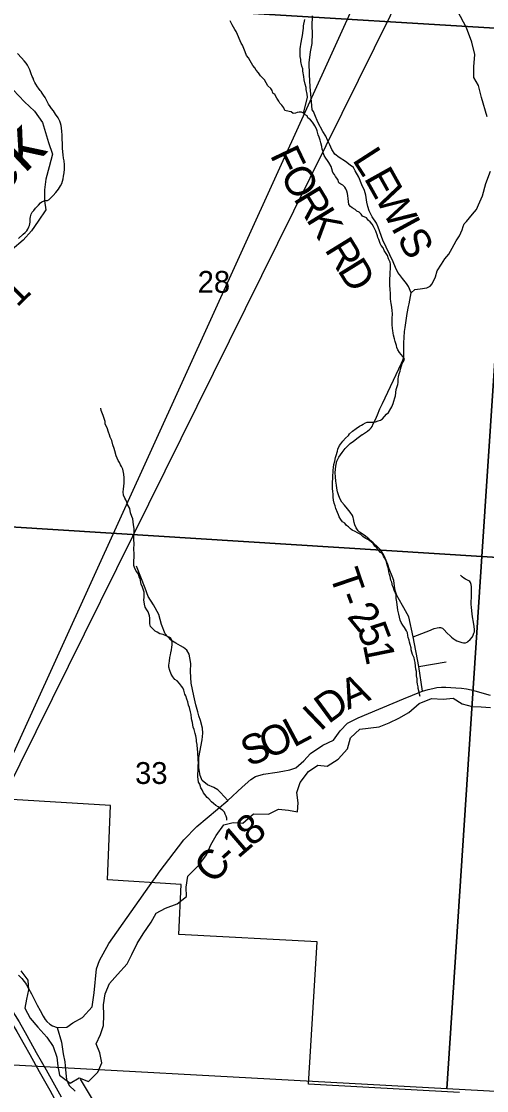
# Model space of a CAD drawing. Extents: x 0 to 45.4, y -2.2 to 22.
# Drawn here: x 5.099 to 5.991, y 15.133 to 17.183 of the extents above; entities that cross this region are included whole.
import ezdxf

# ---------------------------------------------------------------- set-up
doc = ezdxf.new("R2010")
doc.units = 0
for name, color, linetype in [('GM_X_Corporation', 7, 'Continuous'), ('GM_X_County_Road', 7, 'Continuous'), ('GM_X_County_Road_Text', 7, 'Continuous'), ('GM_X_Minor_River', 7, 'Continuous'), ('GM_X_Minor_River_Text', 7, 'Continuous'), ('GM_X_Section_Text', 7, 'Continuous'), ('GM_X_Township_Road', 7, 'Continuous'), ('GM_X_Township_Road_Text', 7, 'Continuous'), ('GM_X_US_Route', 7, 'Continuous'), ('SH_Text', 7, 'Continuous')]:
    doc.layers.add(name, color=color, linetype=linetype)

msp = doc.modelspace()

# ---------------------------------------------------------------- linework, layer by layer
at = {"layer": 'GM_X_Corporation'}
for points in [[(5.0121, 18.2353), (6.1142, 18.166), (6.0488, 17.1677), (4.9524, 17.2347)], [(6.0488, 17.1677), (5.9818, 16.1569), (4.8941, 16.2254), (4.9524, 17.2347)], [(7.1661, 17.098), (7.1036, 16.0876), (5.9818, 16.1569), (6.0488, 17.1677)], [(4.8941, 16.2254), (5.9818, 16.1569), (5.9148, 15.1362), (4.837, 15.1953)], [(5.9818, 16.1569), (7.1036, 16.0876), (7.0412, 15.0748), (5.9148, 15.1362)]]:
    msp.add_lwpolyline(points, close=True, dxfattribs=at)
msp.add_lwpolyline([(5.9392, 15.1293), (5.6491, 15.1452), (5.6657, 15.4185), (5.4004, 15.4324), (5.405, 15.5281), (5.2641, 15.5371), (5.2696, 15.6795), (4.8585, 15.7047)], dxfattribs=at)
at = {"layer": 'GM_X_County_Road'}
for points in [[(5.3539, 15.539), (5.3545, 15.5398), (5.3632, 15.5521), (5.4101, 15.6136), (5.4351, 15.6392), (5.4944, 15.6895), (5.5223, 15.7146), (5.5385, 15.7293), (5.5477, 15.7352), (5.5629, 15.74), (5.5893, 15.7436), (5.6001, 15.7452), (5.6134, 15.748), (5.6248, 15.7521), (5.6405, 15.7656), (5.6534, 15.7793), (5.6765, 15.7952), (5.6973, 15.8047), (5.7098, 15.8226), (5.7242, 15.8374), (5.7446, 15.848), (5.8316, 15.8843), (5.8661, 15.8983), (5.868, 15.899)], [(5.868, 15.899), (5.8786, 15.9021), (5.8876, 15.9042), (5.8956, 15.9058), (5.9043, 15.9064), (5.9125, 15.9064), (5.9223, 15.9061), (5.9317, 15.9055), (5.9427, 15.9047), (5.9521, 15.9034), (5.9612, 15.9016), (5.9709, 15.8991), (5.9819, 15.8958), (5.9976, 15.8914)], [(5.0933, 15.3545), (5.0995, 15.3477), (5.104, 15.3422), (5.1062, 15.3389), (5.1083, 15.3356), (5.1123, 15.3287), (5.1181, 15.3185), (5.1234, 15.3082), (5.1289, 15.2967), (5.1344, 15.2866), (5.1405, 15.2757), (5.144, 15.2696), (5.1474, 15.2658), (5.1531, 15.2605), (5.1581, 15.2572), (5.1671, 15.2539), (5.186, 15.2549), (5.1976, 15.2631), (5.2161, 15.2729), (5.2343, 15.2938), (5.2385, 15.3204), (5.243, 15.3664), (5.2487, 15.3827), (5.2665, 15.4154), (5.3522, 15.5366), (5.3539, 15.539)]]:
    msp.add_lwpolyline(points, dxfattribs=at)
at = {"layer": 'GM_X_Minor_River'}
for points in [[(5.7009, 16.8855), (5.6994, 16.8894), (5.6961, 16.8932), (5.6943, 16.9005), (5.6925, 16.9051), (5.6881, 16.9128), (5.6855, 16.9166), (5.6825, 16.9205), (5.6796, 16.9258), (5.6782, 16.93), (5.6767, 16.9346), (5.6753, 16.9381), (5.675, 16.9434), (5.6728, 16.9503), (5.6714, 16.9552), (5.6696, 16.9614), (5.6678, 16.9656), (5.666, 16.9732), (5.6646, 16.977), (5.6613, 16.9828), (5.6594, 16.9862), (5.6572, 16.9901), (5.6531, 16.9943), (5.6483, 16.9982), (5.6468, 17.002), (5.6431, 17.0036), (5.6397, 17.0071), (5.6356, 17.0087), (5.6314, 17.0088), (5.6276, 17.0081), (5.6242, 17.0074), (5.62, 17.0067), (5.6159, 17.0094), (5.6121, 17.0106), (5.6042, 17.0123), (5.6017, 17.0176), (5.5979, 17.0223), (5.5946, 17.0261), (5.5924, 17.0303), (5.5883, 17.0361), (5.5847, 17.0426), (5.5809, 17.0457), (5.5795, 17.0503), (5.5773, 17.0542), (5.5713, 17.0592), (5.5647, 17.0707), (5.5573, 17.0784), (5.5536, 17.0846), (5.5491, 17.0896), (5.5466, 17.0942), (5.5428, 17.0985), (5.5377, 17.1077), (5.534, 17.1134), (5.5307, 17.1177), (5.5281, 17.1246), (5.5227, 17.1372), (5.5201, 17.1414), (5.5183, 17.1456), (5.5132, 17.1579), (5.5103, 17.1636), (5.5077, 17.1675), (5.5029, 17.1767), (5.4989, 17.184)], [(5.6397, 17.0071), (5.647, 17.0344), (5.6471, 17.0378), (5.6468, 17.0435), (5.6451, 17.0526), (5.6451, 17.0564), (5.643, 17.0629), (5.6412, 17.0709), (5.6402, 17.0774), (5.6385, 17.0877), (5.6382, 17.0919), (5.6368, 17.0969), (5.6346, 17.1064), (5.6347, 17.1102), (5.6333, 17.1156), (5.633, 17.119), (5.6335, 17.1262), (5.6336, 17.1308), (5.634, 17.1346), (5.6348, 17.1395), (5.637, 17.1527), (5.6378, 17.1562), (5.6391, 17.1653), (5.6395, 17.1702), (5.64, 17.1744), (5.6425, 17.1865)], [(5.0831, 17.0516), (5.1049, 17.0287), (5.1238, 17.0112), (5.1389, 16.9891), (5.1448, 16.9701), (5.1508, 16.951), (5.1583, 16.9282), (5.1521, 16.9039), (5.1452, 16.8804), (5.1429, 16.8599), (5.1428, 16.8393), (5.1457, 16.8218), (5.1305, 16.7998), (5.1183, 16.7816), (5.1023, 16.7635), (5.0811, 16.746)], [(5.7282, 16.3923), (5.734, 16.3971), (5.7409, 16.4023), (5.7474, 16.4071), (5.7509, 16.4086), (5.7543, 16.4108), (5.7585, 16.4134), (5.762, 16.4145), (5.7661, 16.4148), (5.7737, 16.4147), (5.7775, 16.415), (5.7832, 16.4172), (5.7874, 16.4186), (5.7912, 16.4212), (5.799, 16.4299), (5.8028, 16.4332), (5.8071, 16.4407), (5.8091, 16.4441), (5.8114, 16.4506), (5.813, 16.4551), (5.815, 16.4615), (5.8159, 16.4653), (5.8176, 16.4775), (5.8204, 16.4869), (5.8212, 16.4907), (5.8214, 16.4979), (5.8222, 16.5013), (5.8234, 16.5074), (5.8254, 16.5123), (5.8258, 16.5161), (5.8291, 16.5271), (5.8322, 16.5324), (5.8334, 16.5365), (5.8304, 16.5404), (5.8271, 16.5446), (5.8241, 16.5481), (5.8204, 16.5531), (5.819, 16.5577), (5.8179, 16.5619), (5.8154, 16.5695), (5.8144, 16.5745), (5.8126, 16.5817), (5.8119, 16.5852), (5.8108, 16.5901), (5.8102, 16.5943), (5.8095, 16.602), (5.8097, 16.613), (5.8103, 16.6232), (5.81, 16.6278), (5.809, 16.6354), (5.8076, 16.6423), (5.8073, 16.6457), (5.8066, 16.6511), (5.8067, 16.656), (5.8064, 16.6594), (5.8058, 16.6708), (5.8055, 16.6754), (5.8053, 16.6845), (5.8054, 16.6883), (5.8059, 16.6978), (5.806, 16.7013), (5.8065, 16.7092), (5.8066, 16.7176), (5.8059, 16.7214), (5.803, 16.7275), (5.8005, 16.7344), (5.7968, 16.7402), (5.7942, 16.744), (5.7924, 16.749), (5.7887, 16.7533), (5.7865, 16.7571), (5.7844, 16.7647), (5.7821, 16.7686), (5.7814, 16.772), (5.7786, 16.7808), (5.7764, 16.7847), (5.7742, 16.79), (5.7716, 16.7942), (5.7675, 16.7989), (5.7642, 16.8016), (5.7605, 16.8062), (5.7529, 16.8094), (5.75, 16.8136), (5.7463, 16.8171), (5.7421, 16.8195), (5.7388, 16.8222), (5.7331, 16.8257), (5.7298, 16.828), (5.7268, 16.8323), (5.7258, 16.8376), (5.7251, 16.8433), (5.7245, 16.8486), (5.7238, 16.8528), (5.7227, 16.8578), (5.7209, 16.862), (5.7187, 16.8655), (5.715, 16.869), (5.7112, 16.8709), (5.7075, 16.8733), (5.7057, 16.8798), (5.7009, 16.8855)], [(5.3142, 16.1962), (5.3151, 16.2064), (5.3152, 16.211), (5.3138, 16.2179), (5.3121, 16.2293), (5.3107, 16.2335), (5.3082, 16.2408), (5.3064, 16.2492), (5.3024, 16.2568), (5.3009, 16.2614), (5.2991, 16.2656), (5.2969, 16.2691), (5.2947, 16.2748), (5.2941, 16.2813), (5.2942, 16.2859), (5.2955, 16.298), (5.2956, 16.3045), (5.2957, 16.3079), (5.2954, 16.3148), (5.2944, 16.3182), (5.293, 16.3243), (5.2904, 16.3297), (5.2886, 16.3331), (5.2867, 16.337), (5.2845, 16.3412), (5.2802, 16.3504), (5.278, 16.3599), (5.2766, 16.3641), (5.2741, 16.371), (5.2723, 16.3798), (5.269, 16.3856), (5.2676, 16.3901), (5.2654, 16.3955), (5.2629, 16.4039), (5.2596, 16.4108), (5.259, 16.4161), (5.2557, 16.4272), (5.2514, 16.4372), (5.2507, 16.4418)], [(5.8634, 15.8888), (5.862, 15.8934), (5.8613, 15.8972), (5.8599, 15.9037), (5.8595, 15.9075), (5.8585, 15.9124), (5.8578, 15.9166), (5.8575, 15.9223), (5.8565, 15.9284), (5.8563, 15.9364), (5.8552, 15.941), (5.8546, 15.9471), (5.8539, 15.9536), (5.8529, 15.9589), (5.8518, 15.9631), (5.8489, 15.9693), (5.8474, 15.9738), (5.8464, 15.9784), (5.8461, 15.9822), (5.8443, 15.9883), (5.8432, 15.9929), (5.8422, 15.9964), (5.8407, 16.0021), (5.8397, 16.0059), (5.839, 16.0105), (5.8375, 16.0143), (5.8353, 16.0178), (5.8335, 16.0212), (5.8302, 16.0255), (5.8272, 16.0305), (5.8254, 16.0351), (5.8226, 16.0465), (5.8208, 16.0541), (5.8198, 16.0599), (5.8191, 16.0644), (5.8188, 16.0702), (5.8174, 16.0763), (5.8172, 16.0835), (5.8161, 16.0869), (5.8139, 16.0927), (5.8121, 16.0973), (5.8107, 16.1011), (5.8089, 16.108), (5.8071, 16.1118), (5.8057, 16.1187), (5.8046, 16.1225), (5.8032, 16.1278), (5.8025, 16.1332), (5.8004, 16.1412), (5.7982, 16.1485), (5.7949, 16.1546), (5.7931, 16.158), (5.7909, 16.1619), (5.7871, 16.1646), (5.7827, 16.1696), (5.7801, 16.1735), (5.7764, 16.177), (5.773, 16.182), (5.7667, 16.1874), (5.7633, 16.1897), (5.7581, 16.1921), (5.7536, 16.1952), (5.7499, 16.1991), (5.7431, 16.2022), (5.739, 16.205), (5.7333, 16.2074), (5.73, 16.2101), (5.7263, 16.2139), (5.7221, 16.2167), (5.7188, 16.2209), (5.7147, 16.2236), (5.711, 16.2283), (5.7084, 16.2333), (5.707, 16.2367), (5.7051, 16.2417), (5.7019, 16.249), (5.7004, 16.2543), (5.6986, 16.2593), (5.6972, 16.265), (5.6966, 16.2711), (5.6963, 16.2772), (5.696, 16.281), (5.6954, 16.2879), (5.6956, 16.3004), (5.696, 16.3061), (5.6958, 16.3129), (5.6963, 16.3179), (5.6963, 16.3224), (5.6972, 16.3278), (5.698, 16.3334), (5.6997, 16.3399), (5.7009, 16.3467), (5.7021, 16.3509), (5.7049, 16.3592), (5.7057, 16.3626), (5.7085, 16.3698), (5.7112, 16.3732), (5.7151, 16.3784), (5.7201, 16.384), (5.7263, 16.3889), (5.7282, 16.3923)], [(5.4926, 15.6513), (5.4926, 15.6551), (5.4916, 15.6593), (5.4897, 15.6628), (5.4879, 15.6666), (5.4849, 15.6701), (5.4808, 15.6732), (5.476, 15.6771), (5.4715, 15.6795), (5.467, 15.6837), (5.4633, 15.6864), (5.4584, 15.6926), (5.4547, 15.6953), (5.4506, 15.7007), (5.4477, 15.7042), (5.4455, 15.7095), (5.4429, 15.7134), (5.4407, 15.7203), (5.4385, 15.7241), (5.4372, 15.7352), (5.4375, 15.7519), (5.4379, 15.7557), (5.4381, 15.7621), (5.4377, 15.7659), (5.4375, 15.7732), (5.4372, 15.7774), (5.4373, 15.7827), (5.4366, 15.7872), (5.436, 15.7968), (5.4346, 15.8025), (5.4347, 15.8059), (5.4329, 15.8135), (5.4318, 15.8177), (5.4301, 15.8254), (5.4279, 15.8296), (5.4265, 15.8391), (5.4255, 15.8433), (5.4251, 15.8468), (5.4241, 15.854), (5.4231, 15.859), (5.4213, 15.8673), (5.4191, 15.8719), (5.4181, 15.8784), (5.4159, 15.8838), (5.4142, 15.8899), (5.4123, 15.8934), (5.4102, 15.901), (5.408, 15.9052), (5.4058, 15.9087), (5.4021, 15.9133), (5.3972, 15.9187), (5.3931, 15.9211), (5.389, 15.9261), (5.3857, 15.9318), (5.3832, 15.9387), (5.3814, 15.9452), (5.3815, 15.949), (5.3824, 15.9562), (5.3836, 15.9634), (5.3848, 15.9683), (5.3853, 15.9721), (5.3865, 15.9782), (5.387, 15.9831), (5.3875, 15.9877), (5.3875, 15.9923), (5.3869, 15.9968), (5.3847, 16.001), (5.3775, 16.0046), (5.3704, 16.0074), (5.364, 16.009), (5.3591, 16.0121), (5.355, 16.0141), (5.3494, 16.0199), (5.346, 16.023), (5.345, 16.0283), (5.3452, 16.039), (5.3445, 16.0432), (5.342, 16.0512), (5.3394, 16.055), (5.3361, 16.06), (5.3346, 16.0654), (5.3337, 16.0738), (5.3341, 16.0783), (5.3339, 16.0886), (5.3329, 16.0928), (5.3311, 16.0982), (5.3281, 16.1039), (5.3278, 16.1073), (5.3264, 16.115), (5.3246, 16.1184), (5.3224, 16.1245), (5.3187, 16.1292), (5.3158, 16.1357), (5.3144, 16.1399), (5.3145, 16.1498), (5.315, 16.1543), (5.3152, 16.1638), (5.3145, 16.1695), (5.3147, 16.1832), (5.3144, 16.1878), (5.3142, 16.1962)], [(5.2568, 15.2776), (5.2562, 15.2974), (5.2593, 15.3186), (5.2677, 15.3384), (5.2829, 15.3558), (5.3012, 15.3762), (5.3103, 15.3937), (5.321, 15.4149), (5.3325, 15.4339), (5.3477, 15.4559), (5.3569, 15.4733), (5.3751, 15.4831), (5.3971, 15.4914), (5.4153, 15.505), (5.4146, 15.5233), (5.4178, 15.5445), (5.4391, 15.565), (5.4535, 15.5854), (5.4619, 15.6044), (5.4719, 15.6219), (5.4871, 15.6423), (5.5045, 15.6468), (5.5235, 15.646), (5.544, 15.6634), (5.5728, 15.6633), (5.5917, 15.6724), (5.6107, 15.6708), (5.6281, 15.6677), (5.6297, 15.6851), (5.6267, 15.7049), (5.6336, 15.7239), (5.6496, 15.7451), (5.6671, 15.7572), (5.6852, 15.7549), (5.7065, 15.7685), (5.724, 15.7882), (5.7301, 15.8094), (5.7476, 15.8261), (5.7848, 15.8305), (5.8037, 15.8381), (5.8227, 15.8471), (5.8417, 15.8577), (5.8614, 15.8751), (5.885, 15.8849), (5.9077, 15.8833), (5.9266, 15.8855), (5.944, 15.8748), (5.9629, 15.8694), (5.9803, 15.8686), (5.9985, 15.8678)], [(5.0974, 15.3625), (5.1109, 15.345), (5.1124, 15.326), (5.1085, 15.3085), (5.1054, 15.291), (5.1152, 15.272), (5.1303, 15.2545), (5.1476, 15.2354), (5.1596, 15.2179), (5.1664, 15.1974), (5.1686, 15.1799), (5.1715, 15.1624), (5.1919, 15.1472), (5.2094, 15.1577), (5.2275, 15.1508), (5.245, 15.1683), (5.2527, 15.1865), (5.249, 15.2055), (5.2422, 15.223), (5.2506, 15.2404), (5.256, 15.2579), (5.2568, 15.2776)], [(5.2111, 15.155), (5.2612, 15.0722), (5.2676, 15.0698), (5.2717, 15.0656), (5.2773, 15.0617), (5.2806, 15.059), (5.2844, 15.0574), (5.2889, 15.0566), (5.2939, 15.0572), (5.2977, 15.0583), (5.3045, 15.0586), (5.309, 15.0574)]]:
    msp.add_lwpolyline(points, dxfattribs=at)
at = {"layer": 'GM_X_Township_Road'}
for p, q in [((5.8502, 16.0033), (5.8835, 16.016)), ((5.8611, 15.9463), (5.9131, 15.9551))]:
    msp.add_line(p, q, dxfattribs=at)
for points in [[(5.9918, 16.9998), (5.9809, 17.0373), (5.9754, 17.0602), (5.9662, 17.0757), (5.9662, 17.084), (5.9662, 17.0958), (5.9681, 17.1196), (5.9626, 17.1434), (5.9525, 17.1708), (5.9292, 17.214)], [(5.8412, 16.6362), (5.8423, 16.6418), (5.846, 16.6624), (5.841, 16.6748), (5.837, 16.6807), (5.8296, 16.6899), (5.8236, 16.6975), (5.8208, 16.7015), (5.8159, 16.711), (5.8117, 16.7223), (5.7916, 16.7639), (5.7829, 16.7886), (5.7795, 16.7964), (5.7717, 16.8083), (5.7688, 16.8133), (5.7659, 16.8197), (5.7633, 16.8279), (5.7612, 16.8364), (5.7591, 16.8496), (5.7569, 16.8587), (5.7514, 16.8695), (5.7458, 16.8846), (5.739, 16.8964), (5.7353, 16.903), (5.7295, 16.9073), (5.7203, 16.9142), (5.7082, 16.9218), (5.7001, 16.9284), (5.694, 16.9377), (5.6901, 16.9461), (5.686, 16.9553), (5.6824, 16.9632), (5.6769, 16.9719), (5.6672, 16.9898), (5.6613, 17.004), (5.6588, 17.0101), (5.6565, 17.0133), (5.6555, 17.0219), (5.6523, 17.0577), (5.6513, 17.0811), (5.6506, 17.1038), (5.6534, 17.1247), (5.6561, 17.1405), (5.6568, 17.1606), (5.6565, 17.1741), (5.6568, 17.1939)], [(5.0929, 16.7668), (5.102, 16.7752), (5.1059, 16.7783), (5.1088, 16.7814), (5.1111, 16.7844), (5.1132, 16.789), (5.1142, 16.7919), (5.1148, 16.795), (5.1153, 16.7983), (5.1155, 16.8016), (5.1155, 16.805), (5.1158, 16.8086), (5.1171, 16.8137), (5.1193, 16.8172), (5.1222, 16.8207), (5.1256, 16.8247), (5.1283, 16.8274), (5.1316, 16.831), (5.1353, 16.835), (5.1379, 16.837), (5.1422, 16.8393), (5.1444, 16.8399), (5.1474, 16.8399), (5.1487, 16.8399), (5.1499, 16.8402), (5.1508, 16.8408), (5.1521, 16.8418), (5.1546, 16.8444), (5.1593, 16.8495), (5.1647, 16.8551), (5.1698, 16.8613), (5.1737, 16.8675), (5.176, 16.8721), (5.1774, 16.8766), (5.1786, 16.881), (5.1797, 16.8864), (5.1806, 16.893), (5.181, 16.8998), (5.1811, 16.9035), (5.181, 16.908), (5.1804, 16.916), (5.1794, 16.9211), (5.1785, 16.9274), (5.1779, 16.9328), (5.1776, 16.9402), (5.1773, 16.9494), (5.1769, 16.9568), (5.1768, 16.9657), (5.1764, 16.972), (5.1757, 16.9788), (5.175, 16.9832), (5.1738, 16.9882), (5.1726, 16.9917), (5.1704, 16.9958), (5.1689, 16.9984), (5.1641, 17.0054), (5.1601, 17.0113), (5.1566, 17.0161), (5.1541, 17.0196), (5.1509, 17.0246), (5.144, 17.037), (5.1412, 17.0417), (5.1387, 17.0456), (5.1368, 17.0485), (5.1349, 17.0505), (5.1316, 17.055), (5.1296, 17.0576), (5.1262, 17.0625), (5.1243, 17.0658), (5.1227, 17.0696), (5.121, 17.074), (5.1194, 17.0775), (5.1176, 17.0827), (5.1146, 17.0902), (5.1104, 17.099), (5.1076, 17.1032), (5.104, 17.1073), (5.0989, 17.1131), (5.0914, 17.1218)], [(5.846, 16.6624), (5.8533, 16.6688), (5.8634, 16.6706), (5.8762, 16.6725), (5.8826, 16.6757), (5.8862, 16.6798), (5.8926, 16.6935), (5.8963, 16.7045), (5.9045, 16.7177), (5.9105, 16.7278), (5.9182, 16.7369), (5.9246, 16.7484), (5.9324, 16.7621), (5.9388, 16.7721), (5.9443, 16.7831), (5.9461, 16.79), (5.9479, 16.795), (5.9525, 16.7996), (5.964, 16.8133), (5.9713, 16.8224), (5.9754, 16.8316), (5.9827, 16.8489), (5.9896, 16.8723), (5.9982, 16.896)], [(5.7686, 16.1874), (5.7647, 16.1907), (5.7562, 16.1977), (5.7472, 16.204), (5.7443, 16.2066), (5.7408, 16.2123), (5.7382, 16.2177), (5.7369, 16.2224), (5.7355, 16.2291), (5.7352, 16.2316), (5.7335, 16.2357), (5.7295, 16.2424), (5.7244, 16.2483), (5.7181, 16.2553), (5.713, 16.2615), (5.7093, 16.2684), (5.7069, 16.2755), (5.7052, 16.2812), (5.7038, 16.2883), (5.703, 16.2941), (5.702, 16.3013), (5.7009, 16.31), (5.7005, 16.3174), (5.7013, 16.3243), (5.7017, 16.33), (5.7037, 16.34), (5.7074, 16.3476), (5.7136, 16.3564), (5.7198, 16.3644), (5.729, 16.3735), (5.7353, 16.3781), (5.7443, 16.3851), (5.7525, 16.3909), (5.7528, 16.3912), (5.7549, 16.3925), (5.7625, 16.3977), (5.7667, 16.401), (5.7694, 16.4037), (5.7715, 16.4066), (5.7736, 16.4112), (5.7778, 16.4199), (5.7816, 16.4288), (5.7863, 16.4399), (5.7909, 16.4505), (5.8276, 16.5279), (5.8301, 16.5338), (5.8313, 16.5373), (5.832, 16.5414), (5.8322, 16.5483), (5.8322, 16.5573), (5.8322, 16.5665), (5.8329, 16.5767), (5.8336, 16.5885), (5.8345, 16.5959), (5.8384, 16.6229), (5.8412, 16.6362)], [(5.8013, 16.142), (5.7963, 16.1539), (5.794, 16.1594), (5.79, 16.1661), (5.7869, 16.1704), (5.7819, 16.1757), (5.7733, 16.1835), (5.7686, 16.1874)], [(5.433, 15.8726), (5.4293, 15.8899), (5.4241, 15.9142), (5.423, 15.9367), (5.4235, 15.9519), (5.422, 15.9625), (5.4204, 15.9701), (5.4159, 15.9777), (5.4098, 15.9826), (5.4037, 15.9857), (5.395, 15.9906), (5.3855, 15.9967), (5.3741, 16.0089), (5.3673, 16.0267), (5.3624, 16.0458), (5.3517, 16.0644), (5.3421, 16.0801), (5.3363, 16.0962), (5.3195, 16.1384)], [(5.8352, 16.0532), (5.8324, 16.0584), (5.821, 16.0781), (5.8179, 16.084), (5.8163, 16.0898), (5.8149, 16.096), (5.8138, 16.1056), (5.8127, 16.1111), (5.8098, 16.1192), (5.8041, 16.1336), (5.8013, 16.142)], [(5.8835, 16.016), (5.886, 16.017), (5.8905, 16.0189), (5.8958, 16.0204), (5.9001, 16.0212), (5.9024, 16.0208), (5.9062, 16.0194), (5.9091, 16.017), (5.9155, 16.0104), (5.9208, 16.0052), (5.9238, 16.0025), (5.9269, 15.9997), (5.9307, 15.9972), (5.9341, 15.9957), (5.9379, 15.9942), (5.9432, 15.9924), (5.9466, 15.9914), (5.9485, 15.9914), (5.9505, 15.9913), (5.9536, 15.993), (5.9551, 15.9942), (5.9593, 15.9982), (5.9638, 16.0028), (5.9653, 16.006), (5.9667, 16.0101), (5.9674, 16.0129), (5.9675, 16.0172), (5.9671, 16.0231), (5.9658, 16.0314), (5.9641, 16.0416), (5.9627, 16.0527), (5.9619, 16.06), (5.9615, 16.0652), (5.9615, 16.0717), (5.9616, 16.0781), (5.9617, 16.0845), (5.9618, 16.0991), (5.9615, 16.1036), (5.9602, 16.1073), (5.9587, 16.109), (5.9568, 16.1105), (5.954, 16.1119), (5.9502, 16.1138), (5.9472, 16.1154), (5.9439, 16.1178), (5.9411, 16.1213)], [(5.868, 15.899), (5.8611, 15.9463), (5.8502, 16.0033), (5.8416, 16.0413), (5.8352, 16.0532)], [(5.4944, 15.6895), (5.4808, 15.7049), (5.4754, 15.71), (5.4677, 15.7141), (5.4559, 15.719), (5.4454, 15.7277), (5.4413, 15.737), (5.4392, 15.7521), (5.4387, 15.7716), (5.4451, 15.8055), (5.4464, 15.8183), (5.4459, 15.8281), (5.4421, 15.8428), (5.4388, 15.8514), (5.4371, 15.8591), (5.433, 15.8726)], [(5.1671, 15.2539), (5.1754, 15.2259), (5.1789, 15.2036), (5.1818, 15.1879), (5.1832, 15.1728), (5.1854, 15.1542), (5.1904, 15.1427), (5.2019, 15.1319)]]:
    msp.add_lwpolyline(points, dxfattribs=at)
at = {"layer": 'GM_X_US_Route'}
for points in [[(5.0313, 15.3562), (5.0484, 15.334), (5.0657, 15.3098), (5.0792, 15.2894), (5.0945, 15.2646), (5.1091, 15.2388), (5.1272, 15.2064), (5.1461, 15.1731), (5.1749, 15.1208)], [(5.0831, 15.2576), (5.0899, 15.2462), (5.104, 15.2215), (5.1149, 15.2021), (5.133, 15.1697), (5.1532, 15.134), (5.1673, 15.1078)]]:
    msp.add_lwpolyline(points, dxfattribs=at)
at = {"layer": 'SH_Text'}
msp.add_lwpolyline([(7.4129, 20.9), (4.8173, 15.1976), (7.4129, 20.4406)], close=True, dxfattribs=at)

# ---------------------------------------------------------------- texts
at = {"layer": 'GM_X_County_Road_Text'}
for s, rotation, p in [('A', 23.6227, (5.7249, 15.8628)), ('D', 36.2524, (5.6875, 15.8349)), ('I', 43.7313, (5.6721, 15.82)), ('O', 23.0796, (5.57, 15.7682)), ('L', 27.9642, (5.6208, 15.7901)), ('S', 22.9889, (5.5346, 15.7532)), ('8', 40.3495, (5.5405, 15.5993)), ('1', 40.6202, (5.514, 15.5766)), ('C', 50.205, (5.4685, 15.5269)), ('-', 41.8567, (5.4969, 15.5612))]:
    msp.add_text(s, height=0.0568, rotation=rotation, dxfattribs=at).set_placement(p)
at = {"layer": 'GM_X_Minor_River_Text'}
msp.add_text('Creek', height=0.09474, rotation=43.2807, dxfattribs=at).set_placement((4.9045, 16.702))
at = {"layer": 'GM_X_Section_Text'}
for s, p in [('28', (5.4367, 16.6627)), ('33', (5.3167, 15.721))]:
    msp.add_text(s, height=0.04186, rotation=0, dxfattribs=at).set_placement(p)
at = {"layer": 'GM_X_Township_Road_Text'}
for s, rotation, p in [('F', 295.4616, (5.5747, 16.9269)), ('L', 302.7784, (5.7322, 16.9176)), ('O', 300.1858, (5.5936, 16.8878)), ('E', 299.2234, (5.7547, 16.8827)), ('W', 298.5611, (5.7754, 16.8457)), ('R', 301.3419, (5.6194, 16.8435)), ('K', 301.5658, (5.6438, 16.8034)), ('I', 298.5583, (5.8068, 16.7879)), ('R', 301.5938, (5.6791, 16.7458)), ('S', 298.5543, (5.818, 16.7674)), ('D', 301.7555, (5.7037, 16.7059)), ('1', 44.7226, (5.0902, 16.6331)), ('T', 288.8339, (5.6891, 16.1227)), ('-', 290.6471, (5.7035, 16.0806)), ('2', 309.2786, (5.7217, 16.0414)), ('5', 290.818, (5.7415, 16.0185)), ('1', 281.4519, (5.7532, 15.9881))]:
    msp.add_text(s, height=0.0568, rotation=rotation, dxfattribs=at).set_placement(p)

doc.saveas('drawing.dxf')
